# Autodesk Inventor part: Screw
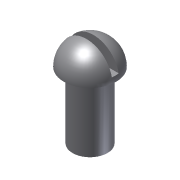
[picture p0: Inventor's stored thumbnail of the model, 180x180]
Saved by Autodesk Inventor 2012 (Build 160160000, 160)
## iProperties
Created: 2009-04
Part Number: Screw
Document SubType Name: Modeling
Designer: Sham
Density: 1 g/cm^3
Material: Default
Author: Sham
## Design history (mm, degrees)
sketch "Sketch1"
  geometry: C1 r 10 at (0, 0)
  constraints: 1 centre point
  dimensions: "d0" = 20 diameter of C1
extrude "Extrusion1" new body sketch "Sketch1" distance "d1" = 38; taper "d2" = 0 deg
sketch "Sketch2"
  geometry: L1 (0, 38)-(-15, 38); L2 (-10, 38)-(10, 38) reference; L3 (0, 38)-(0, 53); A1 r 15 centre (0, 38) between (0, 53) and (-15, 38)
  constraints: 4 end point, 2 point on circle, 1 centre point, 1 collinear, 1 perpendicular
  dimensions: "d3" = 15 radius of A1
revolve "Revolution1" sketch "Sketch2" stored, may be unused: angle "d4" = 90 deg
sketch "Sketch3"
  geometry: L1 (2, 54)-(2, 41); L2 (2, 41)-(-2, 41); L3 (-2, 41)-(-2, 54); L4 (-2, 54)-(2, 54); L5 (15, 38)-(-15, 38) reference
  constraints: 8 end point, 2 parallel, 1 perpendicular, 1 vertical
  dimensions: "d5" = 3 distance between parallel lines of L5 L2; "d6" = 4 distance between parallel lines of L3 L1
extrude "Extrusion2" cut sketch "Sketch3" stored distance "d7" = 38; taper "d8" = 0 deg
body "Solid1"
